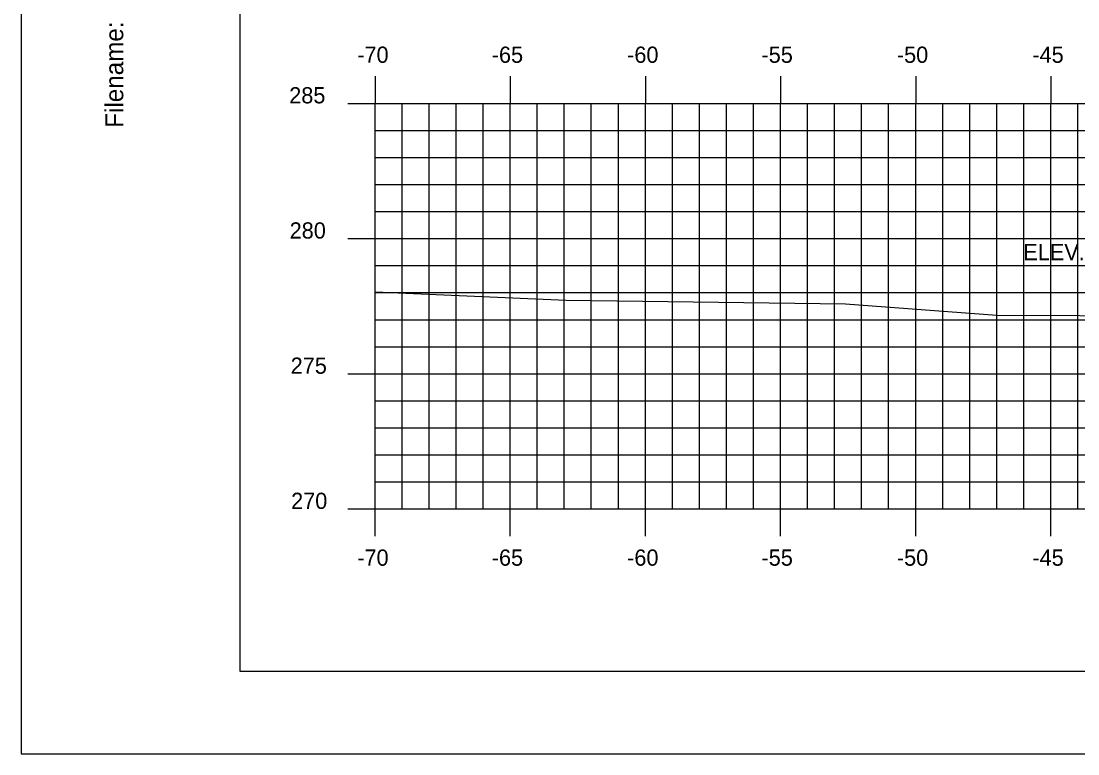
# Model space of a CAD drawing. Extents: x 853563 to 853733, y 366268 to 366378.
# Drawn here: x 853562.67 to 853601.77, y 366268.18 to 366295.28 of the extents above; entities that cross this region are included whole.
import ezdxf

# ---------------------------------------------------------------- set-up
doc = ezdxf.new("R2010")
doc.units = 0
for name, color, linetype in [('BORDER', 7, 'Continuous'), ('D_Text_Standard', 7, 'Continuous'), ('H_V ANNOTATION', 7, 'Continuous'), ('MAJOR', 7, 'Continuous'), ('MINOR', 7, 'Continuous'), ('PLOT BOUNDARY', 7, 'Continuous'), ('S_Roadway_Centerline', 7, 'Continuous')]:
    doc.layers.add(name, color=color, linetype=linetype)

msp = doc.modelspace()

# ---------------------------------------------------------------- linework, layer by layer
at = {"layer": 'BORDER'}
for p, q in [((853570.768, 366376.236), (853570.768, 366271.236)), ((853570.768, 366271.236), (853730.768, 366271.236))]:
    msp.add_line(p, q, dxfattribs=at)
at = {"layer": 'MAJOR'}
for p, q in [((853575.768, 366293.238), (853575.768, 366292.236)), ((853580.768, 366293.238), (853580.768, 366292.236)), ((853585.768, 366293.238), (853585.768, 366292.236)), ((853590.768, 366293.238), (853590.768, 366292.236)), ((853595.768, 366293.238), (853595.768, 366292.236)), ((853600.768, 366293.238), (853600.768, 366292.236)), ((853574.766, 366292.236), (853575.768, 366292.236)), ((853575.768, 366292.236), (853715.768, 366292.236)), ((853575.768, 366277.236), (853575.768, 366292.236)), ((853575.768, 366277.236), (853575.768, 366292.236)), ((853575.768, 366292.236), (853715.768, 366292.236)), ((853580.768, 366277.236), (853580.768, 366292.236)), ((853585.768, 366277.236), (853585.768, 366292.236)), ((853590.768, 366277.236), (853590.768, 366292.236)), ((853595.768, 366277.236), (853595.768, 366292.236)), ((853600.768, 366277.236), (853600.768, 366292.236)), ((853574.766, 366287.236), (853575.768, 366287.236)), ((853575.768, 366287.236), (853715.768, 366287.236)), ((853574.766, 366282.236), (853575.768, 366282.236)), ((853575.768, 366282.236), (853715.768, 366282.236)), ((853574.766, 366277.236), (853575.768, 366277.236)), ((853575.768, 366277.236), (853715.768, 366277.236)), ((853575.768, 366277.236), (853715.768, 366277.236)), ((853575.768, 366276.234), (853575.768, 366277.236)), ((853580.768, 366276.234), (853580.768, 366277.236)), ((853585.768, 366276.234), (853585.768, 366277.236)), ((853590.768, 366276.234), (853590.768, 366277.236)), ((853595.768, 366276.234), (853595.768, 366277.236)), ((853600.768, 366276.234), (853600.768, 366277.236))]:
    msp.add_line(p, q, dxfattribs=at)
at = {"layer": 'MINOR'}
for p, q in [((853576.768, 366277.236), (853576.768, 366292.236)), ((853577.768, 366277.236), (853577.768, 366292.236)), ((853578.768, 366277.236), (853578.768, 366292.236)), ((853579.768, 366277.236), (853579.768, 366292.236)), ((853581.768, 366277.236), (853581.768, 366292.236)), ((853582.768, 366277.236), (853582.768, 366292.236)), ((853583.768, 366277.236), (853583.768, 366292.236)), ((853584.768, 366277.236), (853584.768, 366292.236)), ((853586.768, 366277.236), (853586.768, 366292.236)), ((853587.768, 366277.236), (853587.768, 366292.236)), ((853588.768, 366277.236), (853588.768, 366292.236)), ((853589.768, 366277.236), (853589.768, 366292.236)), ((853591.768, 366277.236), (853591.768, 366292.236)), ((853592.768, 366277.236), (853592.768, 366292.236)), ((853593.768, 366277.236), (853593.768, 366292.236)), ((853594.768, 366277.236), (853594.768, 366292.236)), ((853596.768, 366277.236), (853596.768, 366292.236)), ((853597.768, 366277.236), (853597.768, 366292.236)), ((853598.768, 366277.236), (853598.768, 366292.236)), ((853599.768, 366277.236), (853599.768, 366292.236)), ((853601.768, 366277.236), (853601.768, 366292.236)), ((853575.768, 366291.236), (853715.768, 366291.236)), ((853575.768, 366291.236), (853576.77, 366291.236)), ((853575.768, 366290.236), (853715.768, 366290.236)), ((853575.768, 366290.236), (853576.77, 366290.236)), ((853575.768, 366289.236), (853715.768, 366289.236)), ((853575.768, 366289.236), (853576.77, 366289.236)), ((853575.768, 366288.236), (853715.768, 366288.236)), ((853575.768, 366288.236), (853576.77, 366288.236)), ((853575.768, 366286.236), (853715.768, 366286.236)), ((853575.768, 366286.236), (853576.77, 366286.236)), ((853575.768, 366285.236), (853715.768, 366285.236)), ((853575.768, 366285.236), (853576.77, 366285.236)), ((853575.768, 366284.236), (853715.768, 366284.236)), ((853575.768, 366284.236), (853576.77, 366284.236)), ((853575.768, 366283.236), (853715.768, 366283.236)), ((853575.768, 366283.236), (853576.77, 366283.236)), ((853575.768, 366281.236), (853715.768, 366281.236)), ((853575.768, 366281.236), (853576.77, 366281.236)), ((853575.768, 366280.236), (853715.768, 366280.236)), ((853575.768, 366280.236), (853576.77, 366280.236)), ((853575.768, 366279.236), (853715.768, 366279.236)), ((853575.768, 366279.236), (853576.77, 366279.236)), ((853575.768, 366278.236), (853715.768, 366278.236)), ((853575.768, 366278.236), (853576.77, 366278.236))]:
    msp.add_line(p, q, dxfattribs=at)
at = {"layer": 'PLOT BOUNDARY'}
msp.add_lwpolyline([(853562.674, 366268.177), (853732.674, 366268.177), (853732.674, 366378.177), (853562.674, 366378.177)], close=True, dxfattribs=at)
at = {"layer": 'S_Roadway_Centerline'}
msp.add_lwpolyline([(853575.768, 366285.272), (853582.837, 366284.956), (853593.169, 366284.819), (853598.769, 366284.407), (853604.894, 366284.377)], dxfattribs=at)

# ---------------------------------------------------------------- texts
at = {"layer": 'BORDER'}
msp.add_text('Filename:', height=0.6696, rotation=90, dxfattribs=at).set_placement((853566.453, 366291.335))
at = {"layer": 'D_Text_Standard'}
msp.add_text('ELEV. = 276.95', height=0.6, dxfattribs=at).set_placement((853599.749, 366286.436))
at = {"layer": 'H_V ANNOTATION'}
for s, p in [('-70', (853575.109, 366293.736)), ('-65', (853580.085, 366293.736)), ('-60', (853585.093, 366293.736)), ('-55', (853590.064, 366293.736)), ('-50', (853595.072, 366293.736)), ('-45', (853600.085, 366293.736)), ('285', (853572.592, 366292.236)), ('280', (853572.608, 366287.236)), ('275', (853572.646, 366282.236)), ('270', (853572.662, 366277.236)), ('-70', (853575.109, 366275.136)), ('-65', (853580.085, 366275.136)), ('-60', (853585.093, 366275.136)), ('-55', (853590.064, 366275.136)), ('-50', (853595.072, 366275.136)), ('-45', (853600.085, 366275.136))]:
    msp.add_text(s, height=0.6, dxfattribs=at).set_placement(p)
at = {"layer": 'MAJOR'}
msp.add_text('-', height=0.00000006, rotation=53.1301, dxfattribs=at).set_placement((853575.763, 366277.236))

doc.saveas('drawing.dxf')
